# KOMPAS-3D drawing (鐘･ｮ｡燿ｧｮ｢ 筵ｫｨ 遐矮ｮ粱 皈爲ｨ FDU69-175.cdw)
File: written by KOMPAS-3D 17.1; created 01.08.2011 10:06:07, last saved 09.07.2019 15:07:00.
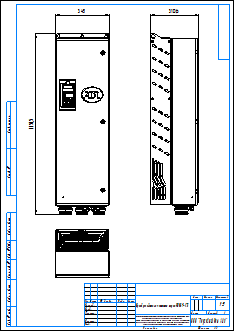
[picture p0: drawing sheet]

Title block, sheet 1: name: Преобразователи частоты серии FDU69-175; scale: 1:5; sheets: 1; sheet format: A3; stored path: \\adlc.lan\data\АДЛ_ПКД\3D-модели\Поставщики\Оборудование Emotron\Преобразователи частоты\Серия FDU 2.0\KOMPAS 2D\Преобразователи частоты серии FDU69-175.cdw

Views: Спереди 1
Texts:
  Рама для чертежей
  Лит-Масса-Масштаб
  Материал-Предприятие
  Масштаб
  Изм.
  Лист
  № докум.
  Подп.
  Дата
  Лит.
  Разраб.
  Пров.
  Т.контр.
  Листов
  Внимание! Данный продукт является объектом авторского права ООО «Торговый Дом АДЛ».
  Запрещается изменение, копирование, распространение
  (в том числе путем копирования на другие сайты и ресурсы в Интернете)
  или любое иное использование информации и объектов без предварительного
  согласия правообладателя (ООО «Торговый Дом АДЛ»).
  Н.контр.
  Утв.
  ООО "Торговый дом АДЛ"
  Изменение
  Номер документа
  Подпись
  Обозначение документа
  Наименование изделия
  Масса изделия по ГОСТ 2.109-73
  Порядковый номер листа
  Общее количество листов в документе
  Характер работы, выполненной лицом, подписавшим документ
  Наименование или индекс предприятия, выпускающего документ
  Инв. № подл.
  Подп. и дата
  Взам. инв. №
  Инв. № дубл.
  Инвентарный номер подлинника по ГОСТ 2.501-68
  Подпись принявшего подлинник в отдел технической документации
  Инвентарный номер подлинника, взамен которого выпущен данный подлинник
  Инвентарный номер дубликата по ГОСТ 2.502-68
  Подпись принявшего дубликат в отдел технической документации
  Справ. №
  Перв. примен.
  Обозначение документа, взамен или на основании которого выпущен данный документ
  Обозначение документа, в котором впервые записан данный документ
  Подпись лица, копировавшего чертеж
  Обозначение формата листа
  !Рама для чертежа
Dimensions and other numbers on the sheet: 1151,5; 345; 310,6; 1:5; 1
